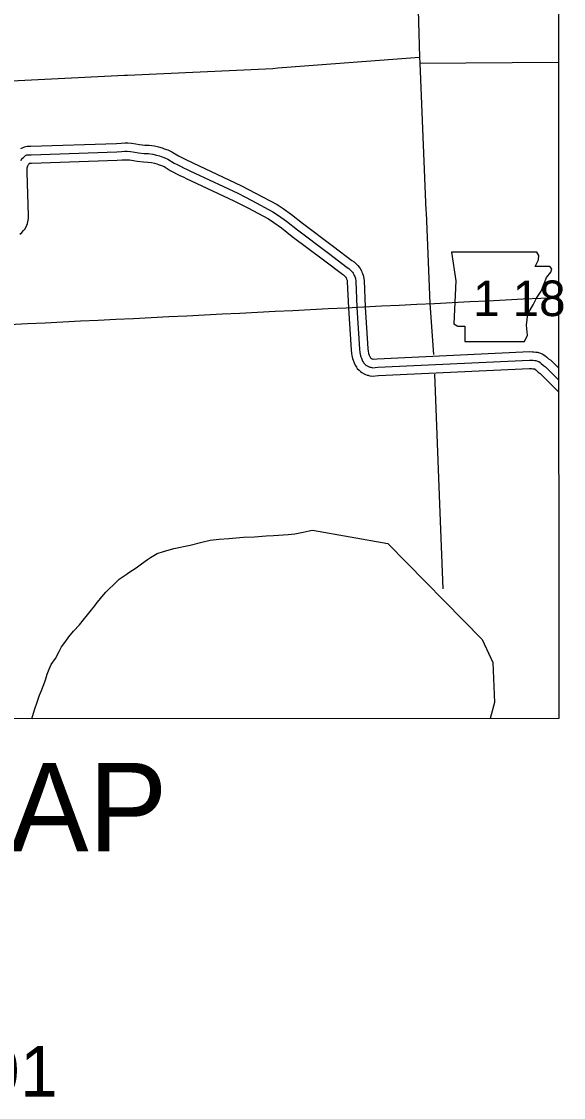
# Model space of a CAD drawing. Extents: x 2520745 to 2582119, y -1491628 to -1461664.
# Drawn here: x 2528934 to 2532155, y -1474299 to -1467904 of the extents above; entities that cross this region are included whole.
import ezdxf

# ---------------------------------------------------------------- set-up
doc = ezdxf.new("R2010")
doc.units = 0
for name, color, linetype in [('1', 7, 'Continuous'), ('10', 7, 'Continuous'), ('21', 7, 'Continuous'), ('3', 7, 'Continuous'), ('4', 7, 'Continuous'), ('59', 7, 'Continuous'), ('60', 7, 'Continuous'), ('R_Draft', 7, 'Continuous')]:
    doc.layers.add(name, color=color, linetype=linetype)

msp = doc.modelspace()

# ---------------------------------------------------------------- linework, layer by layer
at = {"layer": '1'}
msp.add_lwpolyline([(2520744.9, -1463342.8), (2532121.5, -1463335.8), (2532126.8, -1472046.5), (2520750.2, -1472053.4)], close=True, dxfattribs=at)
at = {"layer": '10'}
for points in [[(2528930.7, -1468658.4), (2528943.4, -1468652.4), (2528952.7, -1468649.3), (2528967.6, -1468645.7), (2528983.6, -1468646), (2528988.9, -1468645.7), (2529498, -1468628.4), (2529526.4, -1468626.6), (2529547.5, -1468625.7), (2529565.4, -1468625.4), (2529588.6, -1468628), (2529613.6, -1468631.4), (2529636.1, -1468634.5), (2529666.7, -1468638.8), (2529693.7, -1468639.7), (2529724.3, -1468643.9), (2529748.5, -1468649.5), (2529770.5, -1468655.7), (2529781.5, -1468660), (2529803, -1468666.9), (2529828.2, -1468678.3), (2529867, -1468702.2), (2529882.7, -1468710.4), (2529902.2, -1468720.5), (2529918.5, -1468729.3), (2529940.7, -1468739), (2529956, -1468746.6), (2529985.1, -1468759.9), (2530241, -1468880.4), (2530325.5, -1468924), (2530454.2, -1468992.1), (2530490, -1469016.5), (2530539.5, -1469051), (2530604.7, -1469102.5), (2530789, -1469241.8), (2530897.8, -1469324.1), (2530912.1, -1469332.8), (2530923.4, -1469345.2), (2530926.7, -1469348.4), (2530933.9, -1469355.1), (2530940.7, -1469363.5), (2530947.5, -1469372.2), (2530954.4, -1469385.8), (2530957.5, -1469393.1), (2530961.6, -1469401.6), (2530964.4, -1469412.1), (2530967.3, -1469422.6), (2530970, -1469443.7), (2530977.1, -1469602.2)], [(2528923.3, -1469168.9), (2528936.7, -1469158.1), (2528945.5, -1469146.9), (2528953.1, -1469137.8), (2528962.4, -1469124.3), (2528970.2, -1469105.3), (2528972.5, -1469094), (2528973.3, -1469085.2), (2528974.7, -1469076), (2528975.9, -1469060.1), (2528967.8, -1468799.7), (2528967.1, -1468783.9), (2528967.8, -1468777.2), (2528968.4, -1468774.6), (2528969.5, -1468767.9), (2528971.9, -1468761.7), (2528976, -1468753.7), (2528977.1, -1468751.3), (2528978.6, -1468749.5), (2528979.7, -1468748.3), (2528982.3, -1468745.9), (2528984.8, -1468746), (2528992.7, -1468745.7), (2529503, -1468728.3), (2529531.7, -1468726.4), (2529550.5, -1468725.6), (2529560.6, -1468725.5), (2529576.2, -1468727.2), (2529600.1, -1468730.5), (2529622.4, -1468733.6), (2529658.1, -1468738.6), (2529685.1, -1468739.4), (2529706.1, -1468742.4), (2529723.6, -1468746.4), (2529738.7, -1468750.7), (2529748.1, -1468754.3), (2529767, -1468760.4), (2529781.2, -1468766.8), (2529817.7, -1468789.3), (2529836.7, -1468799.1), (2529855.3, -1468808.8), (2529874.5, -1468819.3), (2529898.4, -1468829.7), (2529913, -1468836.9), (2529943, -1468850.7), (2530196.8, -1468970.1), (2530279.2, -1469012.6), (2530402.5, -1469077.9), (2530433.2, -1469098.9), (2530479.9, -1469131.4), (2530543.5, -1469181.6), (2530728.7, -1469321.6), (2530841.5, -1469406.8), (2530847.7, -1469410.6), (2530851.1, -1469414.4), (2530857.6, -1469420.7), (2530860.8, -1469423.7), (2530862.4, -1469425.7), (2530862.6, -1469426), (2530863.7, -1469428.2), (2530866.5, -1469434.7), (2530867.5, -1469436.7), (2530867.9, -1469438.1), (2530869, -1469442.1), (2530870.3, -1469452.3), (2530877.2, -1469606.7)], [(2530877.3, -1469607.6), (2530893.1, -1469855.5), (2530895.3, -1469876.8), (2530896.8, -1469890.3), (2530900.4, -1469906.7), (2530905.2, -1469917), (2530907.9, -1469923.7), (2530909.3, -1469927.1), (2530911, -1469933.5), (2530916.3, -1469946.8), (2530924.7, -1469959), (2530929.5, -1469966.2), (2530939.9, -1469976.9), (2530948.6, -1469984.8), (2530956.8, -1469991.1), (2530971.3, -1469999), (2530978.7, -1470001.6), (2530988.9, -1470005.6), (2530993.4, -1470006.7), (2530997.4, -1470007.6), (2531005, -1470009.7), (2531019.1, -1470012.1), (2531054.8, -1470009), (2531952.4, -1469966.3), (2531965.3, -1469967.5), (2531972.9, -1469967.7), (2531978.3, -1469968.2), (2531980.5, -1469968.6), (2531984.1, -1469969.5), (2531984.8, -1469970), (2531990, -1469974.5), (2532005.4, -1469988.7), (2532016.4, -1469995.9), (2532125.6, -1470104.4)], [(2530977.1, -1469601.3), (2530992.8, -1469847.3), (2530994.7, -1469866.1), (2530995.6, -1469874), (2530995.6, -1469874.3), (2530997, -1469877.2), (2531000.7, -1469886.4), (2531004.2, -1469895), (2531005.6, -1469900.1), (2531007.5, -1469902.9), (2531007.6, -1469903), (2531009.4, -1469904.8), (2531012.1, -1469907.3), (2531012.5, -1469907.5), (2531013.9, -1469908), (2531018.6, -1469909.9), (2531022.7, -1469910.9), (2531024.2, -1469911.3), (2531048.1, -1469909.2), (2531954.7, -1469866.1), (2531971.2, -1469867.6), (2531979, -1469867.8), (2531990.9, -1469869), (2532000.2, -1469870.5), (2532018.1, -1469874.8), (2532033.2, -1469881.6), (2532047, -1469891.5), (2532056.7, -1469900.1), (2532067.1, -1469909.6), (2532079.8, -1469917.9), (2532125.5, -1469963.3)]]:
    msp.add_lwpolyline(points, dxfattribs=at)
at = {"layer": '21'}
msp.add_lwpolyline([(2531490, -1469275.8), (2531515.4, -1469444.9), (2531504.3, -1469701.5), (2531526.9, -1469715.6), (2531569.2, -1469715.6), (2531569.2, -1469805.8), (2531924.5, -1469805.6), (2531941.4, -1469769), (2531935.7, -1469709.8), (2531944.1, -1469642.1), (2531975.1, -1469588.5), (2531994.8, -1469549), (2532023, -1469506.7), (2532039.9, -1469461.6), (2532054, -1469424.9), (2532079.4, -1469393.9), (2532085, -1469374.2), (2532073.7, -1469360.1), (2531986.3, -1469360.1), (2532006, -1469320.6), (2532008.8, -1469295.3), (2531997.1, -1469275.8)], close=True, dxfattribs=at)
at = {"layer": '3'}
msp.add_lwpolyline([(2528995.3, -1472048.4), (2529011.2, -1471994.8), (2529028.3, -1471944.2), (2529041.3, -1471908.5), (2529052.4, -1471881.2), (2529072.5, -1471828.2), (2529077.8, -1471811), (2529087.3, -1471784.1), (2529097.8, -1471753.1), (2529111.3, -1471725), (2529135.3, -1471689.4), (2529158.2, -1471649.1), (2529172.4, -1471621.8), (2529196.8, -1471586.5), (2529216, -1471561), (2529242.4, -1471528.7), (2529278.1, -1471489.8), (2529300.3, -1471462.3), (2529326, -1471430), (2529349.5, -1471400.4), (2529370.8, -1471377.6), (2529378.5, -1471365.7), (2529411.8, -1471324.2), (2529436, -1471296.7), (2529456, -1471275.5), (2529479.9, -1471252.6), (2529515.3, -1471218.5), (2529555.5, -1471190.3), (2529572.3, -1471178.6), (2529615.5, -1471150.6), (2529648.1, -1471128.2), (2529683.7, -1471102.4), (2529701.1, -1471089.7), (2529739.8, -1471066.2), (2529777.6, -1471053.8), (2529840, -1471036.2), (2529937.1, -1471015.9), (2530005.8, -1470997.9), (2530054.7, -1470986.6), (2530108.7, -1470981.5), (2530167, -1470976.7), (2530253, -1470969.7), (2530319.4, -1470967.1), (2530389, -1470962.1), (2530432, -1470959), (2530518, -1470953.3), (2530557.7, -1470948.5), (2530607.6, -1470938.9), (2530643.1, -1470930.5), (2530663.1, -1470926.8), (2531111.9, -1471006), (2531671.7, -1471577.2), (2531736, -1471714.9), (2531744.5, -1471951.1), (2531719.2, -1472046.7)], dxfattribs=at)
at = {"layer": '4'}
for points in [[(2531237.4, -1466211.4), (2531243, -1466386.2), (2531275.5, -1467246.8), (2531275.5, -1467271.9), (2531300, -1468116.8), (2531300.8, -1468150.9), (2531337.3, -1469028.4), (2531338.5, -1469039.4), (2531361.3, -1469580.3)], [(2528677.2, -1468267.1), (2529546.6, -1468223.4), (2529563.9, -1468222.3), (2530426.9, -1468182.8), (2530457.7, -1468179.2), (2531300, -1468116.8)], [(2531300.8, -1468150.9), (2532124.4, -1468146.8)], [(2531361.3, -1469580.3), (2531382.5, -1469884.1)], [(2531388.9, -1470001), (2531421.2, -1470823), (2531437.4, -1471276)]]:
    msp.add_lwpolyline(points, dxfattribs=at)
at = {"layer": '59'}
for points in [[(2528931.1, -1468731.7), (2528934.2, -1468725.2), (2528940.8, -1468716.5), (2528944.9, -1468712.4), (2528949.1, -1468708.5), (2528953.6, -1468704.6), (2528958.1, -1468700.8), (2528962, -1468698.9), (2528966.6, -1468697.4), (2528973.2, -1468695.8), (2528984.2, -1468696), (2528990.8, -1468695.7), (2529500.5, -1468678.4), (2529529.1, -1468676.5), (2529549, -1468675.7), (2529563, -1468675.4), (2529582.4, -1468677.6), (2529606.8, -1468680.9), (2529629.3, -1468684), (2529662.4, -1468688.7), (2529689.4, -1468689.5), (2529715.2, -1468693.2), (2529736.1, -1468698), (2529754.6, -1468703.2), (2529764.8, -1468707.2), (2529785, -1468713.7), (2529804.7, -1468722.6), (2529842.3, -1468745.8), (2529859.7, -1468754.7), (2529878.8, -1468764.7), (2529896.5, -1468774.3), (2529919.6, -1468784.4), (2529934.5, -1468791.8), (2529964.1, -1468805.3), (2530218.9, -1468925.2), (2530302.3, -1468968.3), (2530428.4, -1469035), (2530461.6, -1469057.7), (2530509.7, -1469091.2), (2530574.1, -1469142.1), (2530758.9, -1469281.7), (2530869.7, -1469365.4), (2530879.9, -1469371.7), (2530887.3, -1469379.8), (2530892.1, -1469384.6), (2530897.3, -1469389.4), (2530901.5, -1469394.6), (2530905.1, -1469399.1), (2530909.1, -1469407), (2530912, -1469413.9), (2530914.6, -1469419.1), (2530916.2, -1469425.1), (2530918.1, -1469432.4), (2530920.1, -1469448), (2530927.2, -1469604.5)], [(2528931.1, -1468731.7), (2528934.2, -1468725.2), (2528940.8, -1468716.5), (2528944.9, -1468712.4), (2528949.1, -1468708.5), (2528953.6, -1468704.6), (2528958.1, -1468700.8), (2528962, -1468698.9), (2528966.6, -1468697.4), (2528973.2, -1468695.8), (2528984.2, -1468696), (2528990.8, -1468695.7), (2529500.5, -1468678.4), (2529529.1, -1468676.5), (2529549, -1468675.7), (2529563, -1468675.4), (2529582.4, -1468677.6), (2529606.8, -1468680.9), (2529629.3, -1468684), (2529662.4, -1468688.7), (2529689.4, -1468689.5), (2529715.2, -1468693.2), (2529736.1, -1468698), (2529754.6, -1468703.2), (2529764.8, -1468707.2), (2529785, -1468713.7), (2529804.7, -1468722.6), (2529842.3, -1468745.8), (2529859.7, -1468754.7), (2529878.8, -1468764.7), (2529896.5, -1468774.3), (2529919.6, -1468784.4), (2529934.5, -1468791.8), (2529964.1, -1468805.3), (2530218.9, -1468925.2), (2530302.3, -1468968.3), (2530428.4, -1469035), (2530461.6, -1469057.7), (2530509.7, -1469091.2), (2530574.1, -1469142.1), (2530758.9, -1469281.7), (2530869.7, -1469365.4), (2530879.9, -1469371.7), (2530887.3, -1469379.8), (2530892.1, -1469384.6), (2530897.3, -1469389.4), (2530901.5, -1469394.6), (2530905.1, -1469399.1), (2530909.1, -1469407), (2530912, -1469413.9), (2530914.6, -1469419.1), (2530916.2, -1469425.1), (2530918.1, -1469432.4), (2530920.1, -1469448), (2530927.2, -1469604.5)], [(2530927.2, -1469604.5), (2530942.9, -1469851.4), (2530945, -1469871.4), (2530946.2, -1469882.1), (2530948, -1469890.5), (2530951.1, -1469897.1), (2530954.3, -1469905.1), (2530956.7, -1469911.1), (2530958.5, -1469917.7), (2530960.6, -1469923), (2530966.1, -1469931), (2530968.5, -1469934.6), (2530974.7, -1469940.9), (2530980.8, -1469946.4), (2530984.2, -1469949), (2530991.9, -1469953.2), (2530996.3, -1469954.8), (2531003.7, -1469957.7), (2531005, -1469958), (2531010.1, -1469959.3), (2531015.8, -1469960.8), (2531021.1, -1469961.7), (2531051.4, -1469959.1), (2531953.6, -1469916.2), (2531968.3, -1469917.6), (2531975.9, -1469917.8), (2531984.6, -1469918.6), (2531990.3, -1469919.5), (2532001.7, -1469922.3), (2532008.1, -1469925.2), (2532015.9, -1469930.7), (2532023.4, -1469937.3), (2532036.3, -1469949.1), (2532048.1, -1469956.9), (2532125.5, -1470033.9)], [(2530927.2, -1469604.5), (2530942.9, -1469851.4), (2530945, -1469871.4), (2530946.2, -1469882.1), (2530948, -1469890.5), (2530951.1, -1469897.1), (2530954.3, -1469905.1), (2530956.7, -1469911.1), (2530958.5, -1469917.7), (2530960.6, -1469923), (2530966.1, -1469931), (2530968.5, -1469934.6), (2530974.7, -1469940.9), (2530980.8, -1469946.4), (2530984.2, -1469949), (2530991.9, -1469953.2), (2530996.3, -1469954.8), (2531003.7, -1469957.7), (2531005, -1469958), (2531010.1, -1469959.3), (2531015.8, -1469960.8), (2531021.1, -1469961.7), (2531051.4, -1469959.1), (2531953.6, -1469916.2), (2531968.3, -1469917.6), (2531975.9, -1469917.8), (2531984.6, -1469918.6), (2531990.3, -1469919.5), (2532001.7, -1469922.3), (2532008.1, -1469925.2), (2532015.9, -1469930.7), (2532023.4, -1469937.3), (2532036.3, -1469949.1), (2532048.1, -1469956.9), (2532125.5, -1470033.9)]]:
    msp.add_lwpolyline(points, dxfattribs=at)
at = {"layer": '60'}
msp.add_spline([(2520749.1, -1470099.6), (2522564.1, -1470012.5), (2528758.3, -1469710.2), (2532125.3, -1469542.5)], degree=3, dxfattribs=at)

# ---------------------------------------------------------------- texts
at = {"layer": '21'}
msp.add_text('1 18', height=211.2, dxfattribs=at).set_placement((2531617.8, -1469655.1))
at = {"layer": 'R_Draft'}
for s, height, p in [('VICINITY MAP', 525, (2525120, -1472838.2)), ('STA. 7+81.91', 300, (2526684.5, -1474295.2))]:
    msp.add_text(s, height=height, rotation=0.03494, dxfattribs=at).set_placement(p)

doc.saveas('drawing.dxf')
